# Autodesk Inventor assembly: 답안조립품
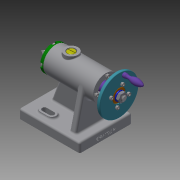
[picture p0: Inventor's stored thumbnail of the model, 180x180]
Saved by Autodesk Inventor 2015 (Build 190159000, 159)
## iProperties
Created: 2022-06
Part Number: 답안조립품
Document SubType Name: Assembly
Designer: 104-111
Author: 104-111
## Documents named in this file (18)
- C:\Users\104-111\Desktop\720606V1011\답안조립품.iam
- C:\Users\104-111\Desktop\720606V1011\나사.ipt
- C:\Users\104-111\Desktop\720606V1011\나사축.ipt
- C:\Users\104-111\Desktop\720606V1011\너트 M8.ipt
- C:\Users\104-111\Desktop\720606V1011\돌림판.ipt
- C:\Users\104-111\Desktop\720606V1011\멈춤나사 M3.ipt
- C:\Users\104-111\Desktop\720606V1011\본체.ipt
- C:\Users\104-111\Desktop\720606V1011\볼트 M3.ipt
- C:\Users\104-111\Desktop\720606V1011\부시.ipt
- C:\Users\104-111\Desktop\720606V1011\센터.ipt
- C:\Users\104-111\Desktop\720606V1011\센터홀더.ipt
- C:\Users\104-111\Desktop\720606V1011\슬리브.ipt
- C:\Users\104-111\Desktop\720606V1011\와셔.ipt
- C:\Users\104-111\Desktop\720606V1011\중공축.ipt
- C:\Users\104-111\Desktop\720606V1011\커버.ipt
- C:\Users\104-111\Desktop\720606V1011\키 4 x 4 x 10.ipt
- C:\Users\104-111\Desktop\720606V1011\플랜지.ipt
- C:\Users\104-111\Desktop\720606V1011\핸들.ipt
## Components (2 placed, 2 different names)
1. 플랜지:1 — 각도:2
2. 핸들:1
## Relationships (1: Angle 1)
- 각도:2 [Angle]: 플랜지:1
